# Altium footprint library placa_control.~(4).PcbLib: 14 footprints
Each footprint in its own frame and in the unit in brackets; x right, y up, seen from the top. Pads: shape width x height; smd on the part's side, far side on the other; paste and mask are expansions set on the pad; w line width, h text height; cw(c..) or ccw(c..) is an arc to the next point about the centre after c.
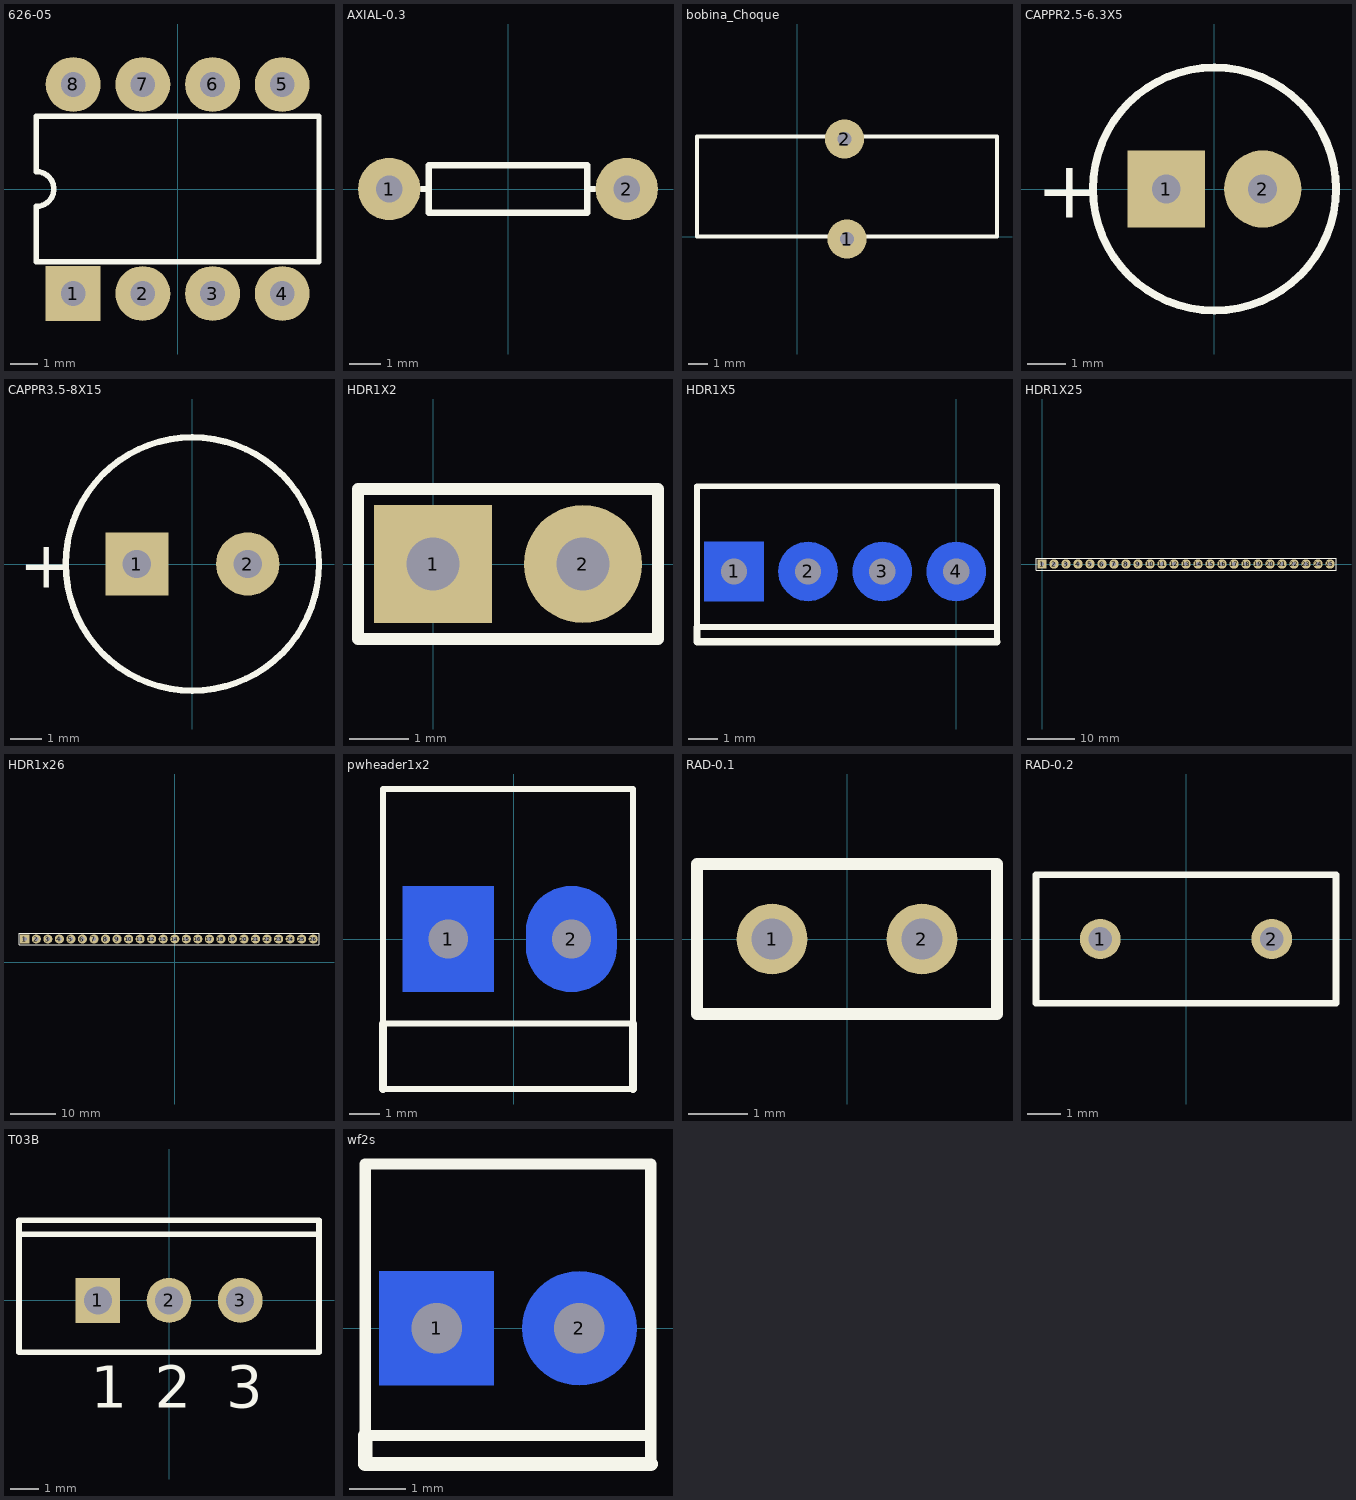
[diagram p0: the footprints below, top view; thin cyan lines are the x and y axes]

## 626-05 [mm] "DIP; 8 Leads; Row Spacing 7.62 mm; Pitch 2.54 mm"
height 4.45
pads (8):
  rect 2x2 hole 0.9: 1(-3.81,-3.81)
  round 2 hole 0.9: 2(-1.27,-3.81) 3(1.27,-3.81) 4(3.81,-3.81) 5(3.81,3.81) 6(1.27,3.81) 7(-1.27,3.81) 8(-3.81,3.81)
Top Overlay:
  lines w0.2: -5.15,-2.65 -5.15,-0.635 ccw(c-5.15,0) -5.15,0.635 -5.15,2.65 5.15,2.65 5.15,-2.65 -5.15,-2.65

## AXIAL-0.3 [mm] "Resistor; 2 Leads"
height 1.524
pads (2):
  round 2 hole 0.85: 1(-3.81,0) 2(3.81,0)
Top Overlay:
  lines w0.2: -2.769,0 -2.54,0 ; 2.769,0 2.54,0 ; 2.54,0 2.54,-0.762 -2.54,-0.762 -2.54,0.762 2.54,0.762 2.54,0

## bobina_Choque [mm]
pads (2):
  round 2 hole 0.7: 1(2.54,-0.127) 2(2.413,4.953)
Top Overlay:
  lines w0.2: -5.08,0 -5.08,5.08 10.16,5.08 10.16,0 -5.08,0

## CAPPR2.5-6.3X5 [mm] "Capacitor, Electrolytic, Radial; Body 6.3 x 5 mm (Dia.xH typ); Pin Spacing 2.5 mm (typ)"
height 6
pads (2):
  rect 2x2 hole 0.75: 1(-1.25,0)
  round 2 hole 0.75: 2(1.25,0)
Top Overlay:
  circle w0.2: c0,0 r3.15
  text "+" at -4.625,-0.75 h1.5

## CAPPR3.5-8X15 [mm] "Capacitor, Electrolytic, Radial; Body 8 x 15 mm (Dia.xH typ); Pin Spacing 3.5 mm (typ)"
height 16.5
pads (2):
  rect 2x2 hole 0.9: 1(-1.75,0)
  round 2 hole 0.9: 2(1.75,0)
Top Overlay:
  circle w0.2: c0,0 r4
  text "+" at -5.475,-0.75 h1.5

## HDR1X2 [mm] "Connector; Header; 2 Position"
pads (2):
  rect 2x2 hole 0.9: 1(0,0)
  round 2 hole 0.9: 2(2.54,0)
Top Overlay:
  lines w0.2: -1.27,-1.27 3.81,-1.27 3.81,1.27 -1.27,1.27 -1.27,-1.27

## HDR1X5 [mil]
pads (4):
  rect 80x80 smd far side: 1(-300,300)
  round 80 smd far side: 2(-200,300) 3(-100,300) 4(0,300)
Top Overlay:
  lines w7.87: 55,205 55,415 -350,415 -350,225 55,225
  lines w10: -350,225 -350,205 55,205

## HDR1X25 [mm] "Connector; Header; 25 Position"
pads (25):
  rect 2x2 hole 0.9: 1(0,0)
  round 2 hole 0.9: 2(2.54,0) 3(5.08,0) 4(7.62,0) 5(10.16,0) 6(12.7,0) 7(15.24,0) 8(17.78,0) 9(20.32,0) 10(22.86,0) 11(25.4,0) 12(27.94,0) 13(30.48,0) 14(33.02,0) 15(35.56,0) 16(38.1,0) 17(40.64,0) 18(43.18,0) 19(45.72,0) 20(48.26,0) 21(50.8,0) 22(53.34,0) 23(55.88,0) 24(58.42,0) 25(60.96,0)
Top Overlay:
  lines w0.2: -1.27,-1.27 -1.27,1.27 0.635,1.27 62.23,1.27 62.23,-1.27 -1.27,-1.27

## HDR1x26 [mm]
pads (26):
  rect 2x2 hole 0.9: 1(-33.02,5.08)
  round 2 hole 0.9: 2(-30.48,5.08) 3(-27.94,5.08) 4(-25.4,5.08) 5(-22.86,5.08) 6(-20.32,5.08) 7(-17.78,5.08) 8(-15.24,5.08) 9(-12.7,5.08) 10(-10.16,5.08) 11(-7.62,5.08) 12(-5.08,5.08) 13(-2.54,5.08) 14(0,5.08) 15(2.54,5.08) 16(5.08,5.08) 17(7.62,5.08) 18(10.16,5.08) 19(12.7,5.08) 20(15.24,5.08) 21(17.78,5.08) 22(20.32,5.08) 23(22.86,5.08) 24(25.4,5.08) 25(27.94,5.08) 26(30.48,5.08)
Top Overlay:
  lines w0.2: -34.29,3.81 -34.29,6.35 -32.385,6.35 31.75,6.35 31.75,3.81 -34.29,3.81

## pwheader1x2 [mm]
pads (2):
  rect 3x3.5 smd far side: 1(-2.159,0)
  oval 3x3.5 smd far side: 2(1.905,0)
Top Overlay:
  lines w0.2: -4.318,-4.953 3.937,-4.953 ; -4.318,-2.794 -4.318,4.953 3.937,4.953 3.937,-2.794 -4.318,-2.794
  lines w0.254: -4.318,-4.953 -4.318,-2.794 ; 3.937,-4.953 3.937,-2.794

## RAD-0.1 [mm] "Indicating Instrument; 2 Leads"
pads (2):
  round 1.2 hole 0.7: 1(-1.27,0) 2(1.27,0)
Top Overlay:
  lines w0.2: -2.54,-1.27 2.54,-1.27 2.54,1.27 -2.54,1.27 -2.54,-1.27

## RAD-0.2 [mm] "Jumper Wire; 2 Leads"
pads (2):
  round 1.2 hole 0.7: 1(-2.54,0) 2(2.54,0)
Top Overlay:
  lines w0.2: -4.445,-1.905 -4.445,1.905 4.445,1.905 4.445,-1.905 -4.445,-1.905

## T03B [mm] "TO, Thru-Hole, Vertical, Heatsink Mounted; 3 In-Line Leads; Pitch 2.54 mm"
height 19.4
pads (3):
  rect 1.6x1.6 hole 1: 1(-2.54,0)
  round 1.6 hole 1: 2(0,0) 3(2.54,0)
Top Overlay:
  lines w0.2: -5.35,2.35 5.35,2.35 ; -5.35,-1.85 5.35,-1.85 5.35,2.85 -5.35,2.85 -5.35,-1.85
  text "2" at -0.5,-3.825 h1.5
  text "1" at -2.79,-3.825 h1.5
  text "3" at 2.04,-3.825 h1.5

## wf2s [mil]
pads (2):
  rect 80x80 smd far side: 1(-300,0)
  round 80 smd far side: 2(-200,0)
Top Overlay:
  lines w7.87: -150,-95 -150,115 -350,115 -350,-75 -150,-75
  lines w10: -350,-75 -350,-95 -150,-95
